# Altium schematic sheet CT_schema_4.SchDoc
size 356 x 211 mm
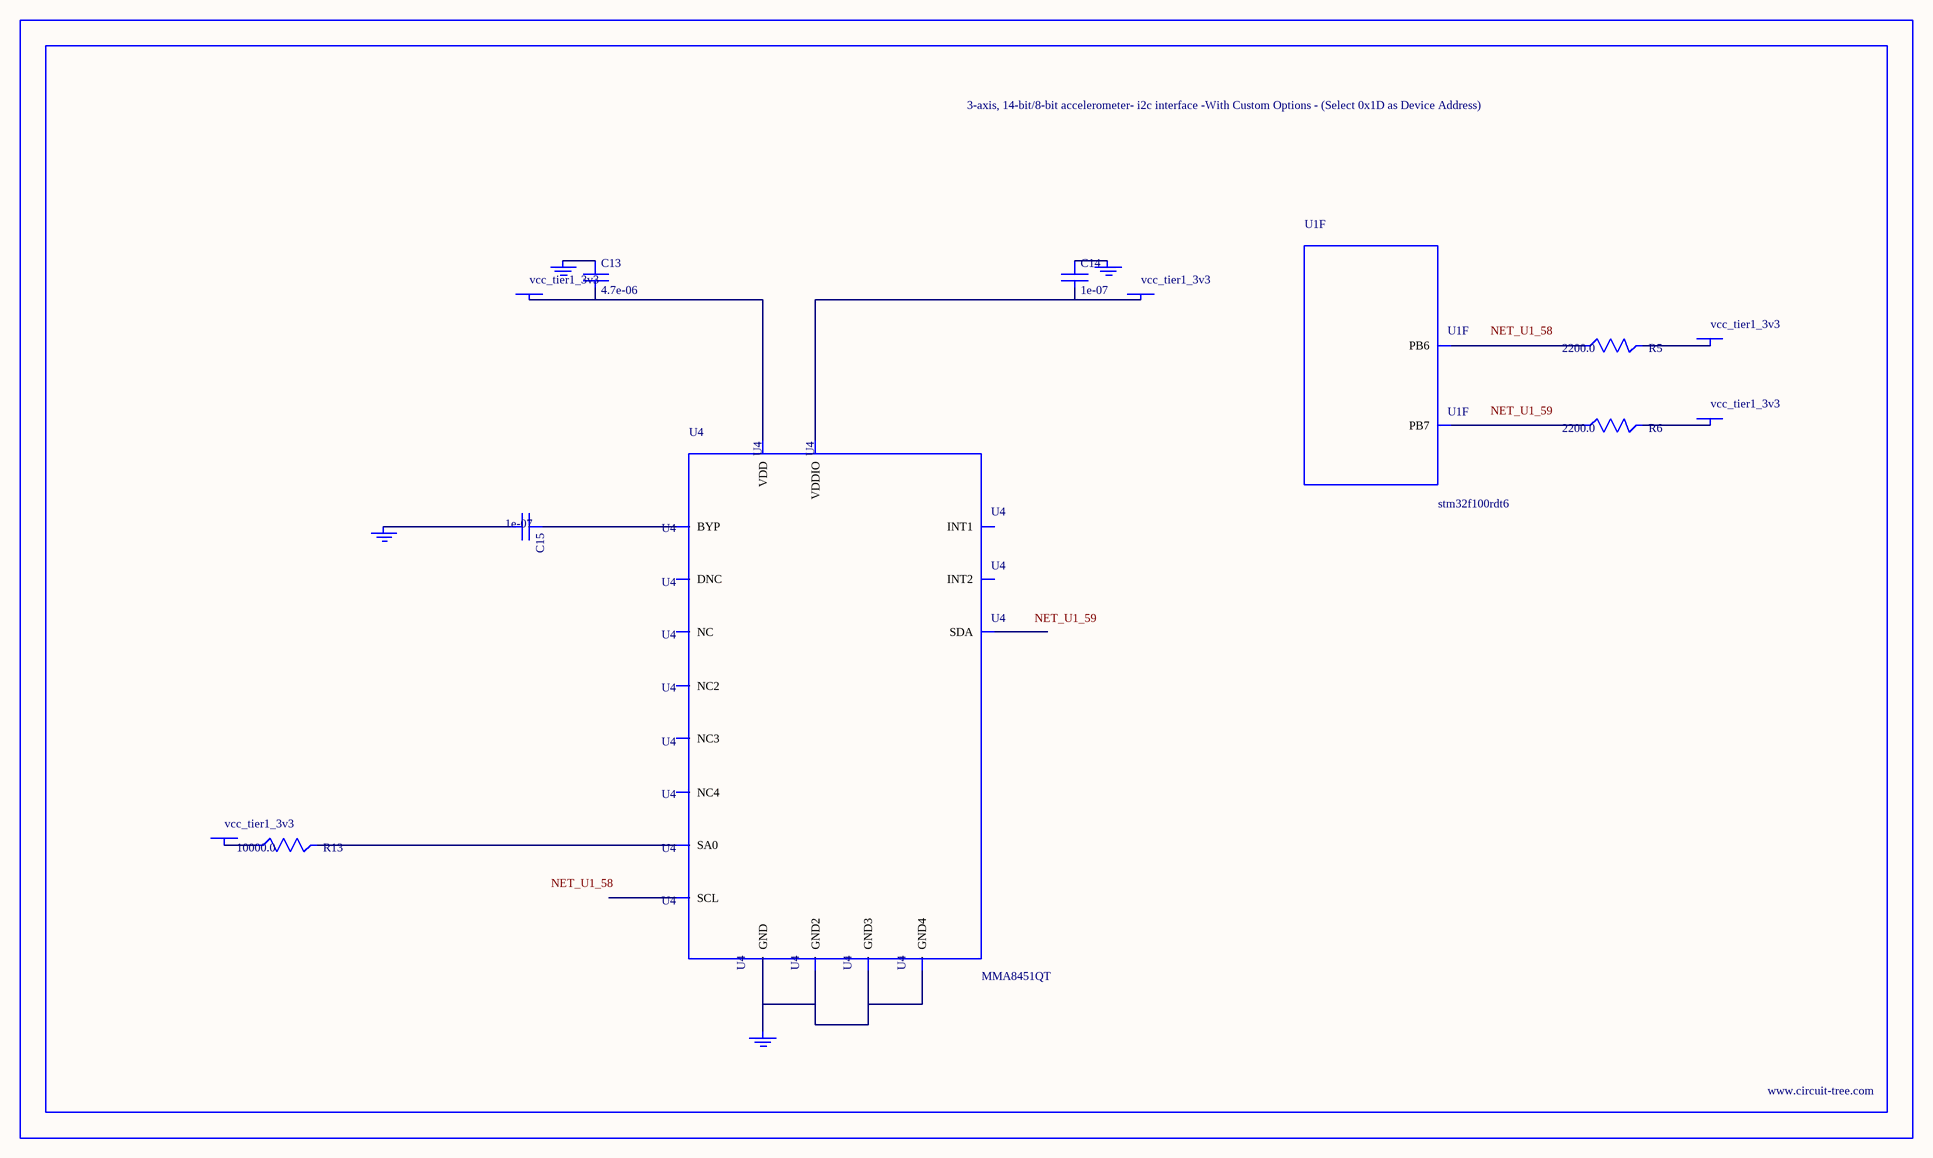
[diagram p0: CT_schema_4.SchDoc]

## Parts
BORDER3  (no value)
C13  4.7e-06  [C0805]
C14  1e-07  [C0402]
C15  1e-07  [C0402]
GND_INSTANCE_3_0  (no value)
GND_INSTANCE_3_1  (no value)
GND_INSTANCE_3_2  (no value)
GND_INSTANCE_3_3  (no value)
POWER_INSTANCE_3_0  vcc_tier1_3v3
POWER_INSTANCE_3_1  vcc_tier1_3v3
POWER_INSTANCE_3_2  vcc_tier1_3v3
POWER_INSTANCE_3_3  vcc_tier1_3v3
POWER_INSTANCE_3_4  vcc_tier1_3v3
R5  2200.0  [R0603]
R6  2200.0  [R0603]
R13  10000.0  [R0603]
U1  stm32f100rdt6  [LQFP64]  (part F of 7)
U4  MMA8451QT  [QFN-16]

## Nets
NetC13_1: C13.1 GND_INSTANCE_3_2.0(GND)
NetC13_2: C13.2 POWER_INSTANCE_3_2.0(PWR) U4.14(VDD)
NetC14_1: C14.1 GND_INSTANCE_3_0.0(GND)
NetC14_2: C14.2 POWER_INSTANCE_3_0.0(PWR) U4.1(VDDIO)
NetC15_1: C15.1 U4.2(BYP)
NetC15_2: C15.2 GND_INSTANCE_3_1.0(GND)
NetGND_INSTANCE_3_3_0: GND_INSTANCE_3_3.0(GND) U4.5(GND) U4.10(GND2) U4.12(GND3) U4.17(GND4)
NetPOWER_INSTANCE_3_1_0: POWER_INSTANCE_3_1.0(PWR) R13.1
NetPOWER_INSTANCE_3_3_0: POWER_INSTANCE_3_3.0(PWR) R5.2
NetPOWER_INSTANCE_3_4_0: POWER_INSTANCE_3_4.0(PWR) R6.2
NetR5_1: R5.1 U1.58(PB6)
NetR6_1: R6.1 U1.59(PB7)
NetR13_2: R13.2 U4.7(SA0)

Not connected (* = marked no-connect by the designer): U4 3(DNC) 4(SCL) 6(SDA) 8(NC) 9(INT2) 11(INT1) 13(NC2) 15(NC3) 16(NC4)

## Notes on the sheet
- Labels drawn without touching a wire or pin: NET_U1_58, NET_U1_59

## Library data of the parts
BORDER3 = BORDER_PAGE3
C13 = C0805C475K4RACTU
C14 C15 = C0402C104K3RACTU
GND_INSTANCE_3_0-GND_INSTANCE_3_3 = GND
POWER_INSTANCE_3_0-POWER_INSTANCE_3_4 = PWR
R5 R6 = RC0603JR-072K2L
R13 = RC0603JR-0710KL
